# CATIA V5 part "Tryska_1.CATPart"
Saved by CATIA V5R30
Part number: Tryska_1
Definition: EH 4200_37_SMM
Nomenclature: EH 4200_37_SMM
Source: Unknown
Description: PART--DESC
Bounding box of the stored display mesh (mm): x 79.15 to 100.85, y -10.848 to 10.848, z -39.3 to 0.7
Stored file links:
  E:\Bakalarka\Model\Forma_v7\Tryska_1.CATPart
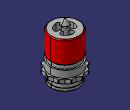
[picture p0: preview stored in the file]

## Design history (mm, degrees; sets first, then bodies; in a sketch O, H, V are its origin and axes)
Body1 "MANIFOLD_SOLID_BREP #3562" (main body)
  Solid1: solid without history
